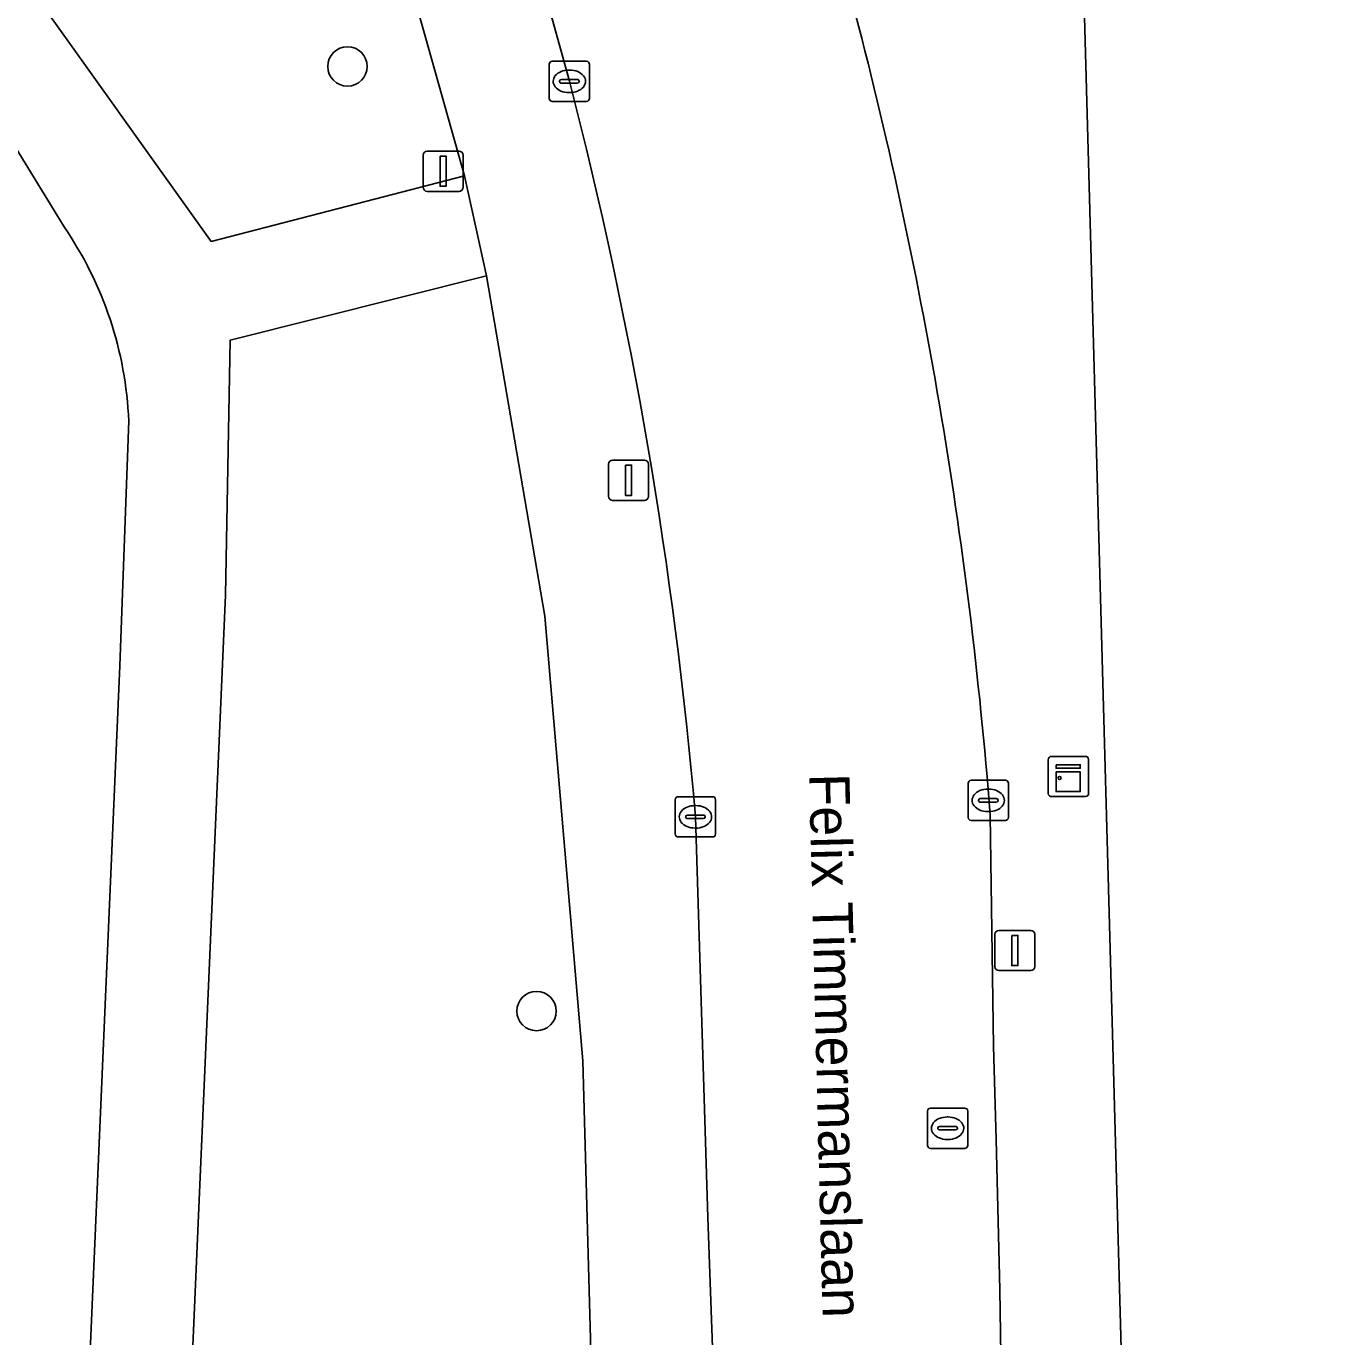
# Model space of a CAD drawing. Extents: x 161258 to 161838, y 380833 to 381727.
# Drawn here: x 161547.08 to 161579.31, y 381304.76 to 381337.3 of the extents above; entities that cross this region are included whole.
import ezdxf

# ---------------------------------------------------------------- set-up
doc = ezdxf.new("R2010")
doc.units = 0
for name, color, linetype in [('IMGEO_Boom', 7, 'Continuous'), ('IMGEO_Erf', 7, 'Continuous'), ('IMGEO_Groenvoorziening', 7, 'Continuous'), ('IMGEO_Kast', 7, 'Continuous'), ('IMGEO_Kolk', 7, 'Continuous'), ('IMGEO_Lichtmast', 7, 'Continuous'), ('IMGEO_Openbare_ruimte_label', 7, 'Continuous'), ('IMGEO_Rijbaan_lokaal_open', 7, 'Continuous'), ('IMGEO_Rioolput', 7, 'Continuous'), ('IMGEO_Verkeersbordpaal', 7, 'Continuous'), ('IMGEO_Voetpad_gesloten', 7, 'Continuous'), ('IMGEO_Voetpad_open', 7, 'Continuous')]:
    doc.layers.add(name, color=color, linetype=linetype)

msp = doc.modelspace()

# ---------------------------------------------------------------- linework, layer by layer
at = {"layer": 'IMGEO_Boom'}
for centre in [(161555.05, 381336.303), (161559.745, 381312.847)]:
    msp.add_circle(centre, 0.489, dxfattribs=at)
at = {"layer": 'IMGEO_Erf'}
msp.add_lwpolyline([(161649.397, 381275.455), (161650.22, 381281.92), (161650.255, 381282.192), (161650.617, 381285.056), (161650.964, 381287.799), (161651.304, 381290.495), (161653.107, 381304.757), (161653.531, 381308.117), (161653.779, 381310.086), (161654.173, 381313.208), (161656.956, 381335.212), (161638.457, 381337.583), (161631.072, 381338.529), (161622.414, 381339.639), (161618.671, 381340.119), (161596.827, 381342.918), (161589.772, 381343.822), (161573.115, 381345.957), (161575.536, 381257.867), (161575.581, 381250), (161575.075, 381232.455), (161573.778, 381197.042)], dxfattribs=at)
at = {"layer": 'IMGEO_Groenvoorziening'}
for points in [[(161548.016, 381332.322), (161543.801, 381339.204), (161540.076, 381345.152), (161529.862, 381362.837), (161527.459, 381367.542), (161522.359, 381377.765), (161521.162, 381381.001), (161516.427, 381396.432), (161510.615, 381415.369), (161509.68, 381415.127)], [(161549.116, 381380.018), (161549.108, 381382.107), (161544.779, 381381.965), (161538.743, 381382.034), (161531.12, 381380.29), (161523.196, 381383.091), (161523.489, 381382.145), (161524.888, 381378.302), (161529.686, 381368.678), (161532.033, 381364.077), (161538.316, 381353.079), (161542.231, 381346.419), (161547.061, 381338.423), (161551.665, 381331.955), (161557.953, 381333.585), (161554.804, 381344.789), (161552.797, 381350.589)], [(161553.579, 381215.917), (161561.286, 381215.348), (161561.314, 381216.115), (161562.157, 381238.191), (161562.402, 381250), (161562.371, 381257.897), (161560.891, 381311.609), (161559.948, 381322.649), (161558.505, 381331.099), (161552.138, 381329.503), (161552.025, 381323.171), (161549.695, 381269.54), (161548.757, 381250), (161548.051, 381233.4)], [(161545.424, 381233.206), (161546.121, 381250), (161547.153, 381269.408), (161549.398, 381321.418), (161549.623, 381327.498)]]:
    msp.add_lwpolyline(points, dxfattribs=at)
msp.add_arc((161540.395, 381327.104), 9.237, 2.4477, 34.4009, dxfattribs=at)
at = {"layer": 'IMGEO_Kast'}
for p, q in [((161572.446, 381318.246), (161572.446, 381319.087)), ((161572.446, 381319.087), (161572.446, 381318.246)), ((161572.521, 381319.171), (161573.362, 381319.171)), ((161573.362, 381319.171), (161572.521, 381319.171)), ((161573.446, 381319.096), (161573.446, 381318.255)), ((161573.446, 381318.255), (161573.446, 381319.096)), ((161573.371, 381318.171), (161572.53, 381318.171)), ((161572.53, 381318.171), (161573.371, 381318.171))]:
    msp.add_line(p, q, dxfattribs=at)
for points in [[(161572.641, 381318.961), (161573.241, 381318.961), (161573.241, 381318.876), (161572.641, 381318.876), (161572.641, 381318.961)], [(161572.641, 381318.786), (161573.241, 381318.786), (161573.241, 381318.297), (161572.641, 381318.297), (161572.641, 381318.786)]]:
    msp.add_lwpolyline(points, dxfattribs=at)
msp.add_circle((161572.725, 381318.635), 0.0377, dxfattribs=at)
for centre, start, end in [((161572.524, 381319.093), 92.4484, 184.2845), ((161572.524, 381319.093), 92.4484, 184.2845), ((161573.368, 381319.093), 2.4484, 94.2845), ((161573.368, 381319.093), 2.4484, 94.2845), ((161572.524, 381318.249), 182.4484, 274.2845), ((161572.524, 381318.249), 182.4484, 274.2845), ((161573.368, 381318.249), 272.4484, 4.2845), ((161573.368, 381318.249), 272.4484, 4.2845)]:
    msp.add_arc(centre, 0.0779, start, end, dxfattribs=at)
at = {"layer": 'IMGEO_Kolk'}
for p, q in [((161560.058, 381335.506), (161560.058, 381336.358)), ((161560.133, 381336.432), (161560.985, 381336.432)), ((161561.059, 381336.358), (161561.059, 381335.506)), ((161560.317, 381335.926), (161560.317, 381335.938)), ((161560.36, 381335.975), (161560.758, 381335.975)), ((161560.546, 381336.212), (161560.571, 381336.212)), ((161560.801, 381335.938), (161560.801, 381335.926)), ((161560.755, 381335.889), (161560.357, 381335.889)), ((161560.569, 381335.652), (161560.544, 381335.652)), ((161560.985, 381335.432), (161560.133, 381335.432)), ((161570.456, 381317.652), (161570.456, 381318.504)), ((161570.531, 381318.578), (161571.383, 381318.578)), ((161570.944, 381318.358), (161570.969, 381318.358)), ((161571.457, 381318.504), (161571.457, 381317.652)), ((161563.187, 381317.243), (161563.187, 381318.095)), ((161563.262, 381318.169), (161564.114, 381318.169)), ((161564.188, 381318.095), (161564.188, 381317.243)), ((161570.715, 381318.072), (161570.715, 381318.084)), ((161571.153, 381318.035), (161570.755, 381318.035)), ((161570.758, 381318.121), (161571.156, 381318.121)), ((161571.199, 381318.084), (161571.199, 381318.072)), ((161563.489, 381317.712), (161563.887, 381317.712)), ((161563.675, 381317.949), (161563.7, 381317.949)), ((161570.967, 381317.798), (161570.942, 381317.798)), ((161563.446, 381317.663), (161563.446, 381317.675)), ((161563.884, 381317.626), (161563.486, 381317.626)), ((161563.698, 381317.389), (161563.673, 381317.389)), ((161563.93, 381317.675), (161563.93, 381317.663)), ((161571.383, 381317.578), (161570.531, 381317.578)), ((161564.114, 381317.169), (161563.262, 381317.169))]:
    msp.add_line(p, q, dxfattribs=at)
for points in [[(161560.058, 381335.506), (161560.058, 381336.358)], [(161560.133, 381336.432), (161560.985, 381336.432)], [(161561.059, 381336.358), (161561.059, 381335.506)], [(161560.985, 381335.432), (161560.133, 381335.432)], [(161570.456, 381317.652), (161570.456, 381318.504)], [(161570.531, 381318.578), (161571.383, 381318.578)], [(161571.457, 381318.504), (161571.457, 381317.652)], [(161563.187, 381317.243), (161563.187, 381318.095)], [(161563.262, 381318.169), (161564.114, 381318.169)], [(161564.188, 381318.095), (161564.188, 381317.243)], [(161571.383, 381317.578), (161570.531, 381317.578)], [(161564.114, 381317.169), (161563.262, 381317.169)]]:
    msp.add_lwpolyline(points, dxfattribs=at)
for centre, radius, start, end in [((161560.135, 381336.356), 0.0765, 91.552, 178.448), ((161560.135, 381336.356), 0.0765, 91.552, 178.448), ((161560.983, 381336.356), 0.0765, 1.552, 88.448), ((161560.983, 381336.356), 0.0765, 1.552, 88.448), ((161560.357, 381335.935), 0.0403, 85.8775, 175.7526), ((161560.354, 381335.925), 0.0366, 178.938, 274.7102), ((161560.758, 381335.932), 0.043, 264.8664, 352.4533), ((161560.762, 381335.937), 0.0386, 1.7309, 96.639), ((161560.135, 381335.508), 0.0765, 181.552, 268.448), ((161560.135, 381335.508), 0.0765, 181.552, 268.448), ((161560.983, 381335.508), 0.0765, 271.552, 358.448), ((161560.983, 381335.508), 0.0765, 271.552, 358.448), ((161570.533, 381318.502), 0.0765, 91.552, 178.448), ((161570.533, 381318.502), 0.0765, 91.552, 178.448), ((161571.381, 381318.502), 0.0765, 1.552, 88.448), ((161571.381, 381318.502), 0.0765, 1.552, 88.448), ((161563.264, 381318.093), 0.0765, 91.552, 178.448), ((161563.264, 381318.093), 0.0765, 91.552, 178.448), ((161564.112, 381318.093), 0.0765, 1.552, 88.448), ((161564.112, 381318.093), 0.0765, 1.552, 88.448), ((161570.755, 381318.081), 0.0403, 85.8775, 175.7526), ((161570.752, 381318.071), 0.0366, 178.938, 274.7102), ((161571.156, 381318.078), 0.043, 264.8664, 352.4533), ((161571.16, 381318.083), 0.0386, 1.7309, 96.639), ((161563.486, 381317.672), 0.0403, 85.8775, 175.7526), ((161563.891, 381317.674), 0.0386, 1.7309, 96.639), ((161563.483, 381317.662), 0.0366, 178.938, 274.7102), ((161563.887, 381317.669), 0.043, 264.8664, 352.4533), ((161570.533, 381317.654), 0.0765, 181.552, 268.448), ((161570.533, 381317.654), 0.0765, 181.552, 268.448), ((161571.381, 381317.654), 0.0765, 271.552, 358.448), ((161571.381, 381317.654), 0.0765, 271.552, 358.448), ((161563.264, 381317.245), 0.0765, 181.552, 268.448), ((161563.264, 381317.245), 0.0765, 181.552, 268.448), ((161564.112, 381317.245), 0.0765, 271.552, 358.448), ((161564.112, 381317.245), 0.0765, 271.552, 358.448)]:
    msp.add_arc(centre, radius, start, end, dxfattribs=at)
for centre, major_axis, ratio, start_param, end_param in [((161560.545, 381335.932), (-0.387, 0.002), 0.722429, 4.712389, 7.853982), ((161560.57, 381335.932), (-0.39, 0.002), 0.717154, 1.570796, 4.712389), ((161570.943, 381318.078), (-0.387, 0.002), 0.722429, 4.712389, 7.853982), ((161570.968, 381318.078), (-0.39, 0.002), 0.717154, 1.570796, 4.712389), ((161563.674, 381317.669), (-0.387, 0.002), 0.722429, 4.712389, 7.853982), ((161563.699, 381317.669), (-0.39, 0.002), 0.717154, 1.570796, 4.712389)]:
    msp.add_ellipse(centre, major_axis=major_axis, ratio=ratio, start_param=start_param, end_param=end_param, dxfattribs=at)
at = {"layer": 'IMGEO_Lichtmast'}
for p, q in [((161561.632, 381326.527), (161562.422, 381326.527)), ((161562.422, 381326.527), (161561.632, 381326.527)), ((161561.532, 381325.627), (161561.532, 381326.427)), ((161561.532, 381326.427), (161561.532, 381325.627)), ((161562.522, 381326.427), (161562.522, 381325.627)), ((161562.522, 381325.627), (161562.522, 381326.427)), ((161562.422, 381325.527), (161561.632, 381325.527)), ((161561.632, 381325.527), (161562.422, 381325.527)), ((161571.221, 381314.85), (161572.011, 381314.85)), ((161572.011, 381314.85), (161571.221, 381314.85)), ((161571.121, 381313.95), (161571.121, 381314.75)), ((161571.121, 381314.75), (161571.121, 381313.95)), ((161572.111, 381314.75), (161572.111, 381313.95)), ((161572.111, 381313.95), (161572.111, 381314.75)), ((161572.011, 381313.85), (161571.221, 381313.85)), ((161571.221, 381313.85), (161572.011, 381313.85))]:
    msp.add_line(p, q, dxfattribs=at)
for points in [[(161561.952, 381326.402), (161562.102, 381326.402), (161562.102, 381325.652), (161561.952, 381325.652), (161561.952, 381326.402)], [(161571.541, 381314.725), (161571.691, 381314.725), (161571.691, 381313.975), (161571.541, 381313.975), (161571.541, 381314.725)]]:
    msp.add_lwpolyline(points, dxfattribs=at)
for centre, start, end in [((161561.632, 381326.427), 90, 180), ((161561.632, 381326.427), 90, 180), ((161562.422, 381326.427), 0, 90), ((161562.422, 381326.427), 360, 90), ((161561.632, 381325.627), 180, 270), ((161561.632, 381325.627), 180, 270), ((161562.422, 381325.627), 270, 0), ((161562.422, 381325.627), 270, 0), ((161571.221, 381314.75), 90, 180), ((161571.221, 381314.75), 90, 180), ((161572.011, 381314.75), 0, 90), ((161572.011, 381314.75), 360, 90), ((161571.221, 381313.95), 180, 270), ((161571.221, 381313.95), 180, 270), ((161572.011, 381313.95), 270, 0), ((161572.011, 381313.95), 270, 0)]:
    msp.add_arc(centre, 0.1, start, end, dxfattribs=at)
at = {"layer": 'IMGEO_Rijbaan_lokaal_open'}
for points in [[(161567.573, 381337.935), (161566.996, 381340.113), (161559.926, 381338.237), (161560.56, 381335.932)], [(161572.007, 381272.353), (161571.937, 381276.234), (161571.841, 381280.385), (161571.71, 381285.385), (161571.552, 381289.803), (161571.367, 381297.22), (161571.333, 381300.008), (161571.247, 381305.925), (161571.149, 381309.659), (161571.088, 381311.972), (161571.005, 381317.713)], [(161563.689, 381317.669), (161563.992, 381307.722), (161564.285, 381299.662), (161564.523, 381289.706), (161564.858, 381278.272), (161564.966, 381273.754), (161565.177, 381265.56), (161565.325, 381258.823), (161565.412, 381254.146), (161565.337, 381250), (161565.241, 381243.283), (161564.974, 381233.421), (161564.784, 381227.236), (161564.503, 381220.58)]]:
    msp.add_lwpolyline(points, dxfattribs=at)
for centre, radius, start, end in [((161457.404, 381308.835), 113.947, 4.46846, 14.79602), ((161452.758, 381308.063), 111.347, 4.9493, 14.49489)]:
    msp.add_arc(centre, radius, start, end, dxfattribs=at)
at = {"layer": 'IMGEO_Rioolput'}
for p, q in [((161569.447, 381309.511), (161569.447, 381310.363)), ((161569.522, 381310.437), (161570.374, 381310.437)), ((161569.935, 381310.217), (161569.96, 381310.217)), ((161570.448, 381310.363), (161570.448, 381309.511)), ((161569.706, 381309.931), (161569.706, 381309.943)), ((161570.144, 381309.894), (161569.746, 381309.894)), ((161569.749, 381309.98), (161570.147, 381309.98)), ((161570.19, 381309.943), (161570.19, 381309.931)), ((161569.958, 381309.657), (161569.933, 381309.657)), ((161570.374, 381309.437), (161569.522, 381309.437))]:
    msp.add_line(p, q, dxfattribs=at)
for points in [[(161569.447, 381309.511), (161569.447, 381310.363)], [(161569.522, 381310.437), (161570.374, 381310.437)], [(161570.448, 381310.363), (161570.448, 381309.511)], [(161570.374, 381309.437), (161569.522, 381309.437)]]:
    msp.add_lwpolyline(points, dxfattribs=at)
for centre, radius, start, end in [((161569.524, 381310.361), 0.0765, 91.552, 178.448), ((161569.524, 381310.361), 0.0765, 91.552, 178.448), ((161570.372, 381310.361), 0.0765, 1.552, 88.448), ((161570.372, 381310.361), 0.0765, 1.552, 88.448), ((161569.746, 381309.94), 0.0403, 85.8775, 175.7526), ((161569.743, 381309.93), 0.0366, 178.938, 274.7102), ((161570.147, 381309.937), 0.043, 264.8664, 352.4533), ((161570.151, 381309.942), 0.0386, 1.7309, 96.639), ((161569.524, 381309.513), 0.0765, 181.552, 268.448), ((161569.524, 381309.513), 0.0765, 181.552, 268.448), ((161570.372, 381309.513), 0.0765, 271.552, 358.448), ((161570.372, 381309.513), 0.0765, 271.552, 358.448)]:
    msp.add_arc(centre, radius, start, end, dxfattribs=at)
for centre, major_axis, ratio, start_param, end_param in [((161569.934, 381309.937), (-0.387, 0.002), 0.722429, 4.712389, 7.853982), ((161569.959, 381309.937), (-0.39, 0.002), 0.717154, 1.570796, 4.712389)]:
    msp.add_ellipse(centre, major_axis=major_axis, ratio=ratio, start_param=start_param, end_param=end_param, dxfattribs=at)
at = {"layer": 'IMGEO_Verkeersbordpaal'}
for p, q in [((161556.931, 381333.3), (161556.931, 381334.1)), ((161556.931, 381334.1), (161556.931, 381333.3)), ((161557.031, 381334.2), (161557.821, 381334.2)), ((161557.821, 381334.2), (161557.031, 381334.2)), ((161557.921, 381334.1), (161557.921, 381333.3)), ((161557.921, 381333.3), (161557.921, 381334.1)), ((161557.821, 381333.2), (161557.031, 381333.2)), ((161557.031, 381333.2), (161557.821, 381333.2))]:
    msp.add_line(p, q, dxfattribs=at)
msp.add_lwpolyline([(161557.351, 381334.075), (161557.501, 381334.075), (161557.501, 381333.325), (161557.351, 381333.325), (161557.351, 381334.075)], dxfattribs=at)
for centre, start, end in [((161557.031, 381334.1), 90, 180), ((161557.031, 381334.1), 90, 180), ((161557.821, 381334.1), 0, 90), ((161557.821, 381334.1), 360, 90), ((161557.031, 381333.3), 180, 270), ((161557.031, 381333.3), 180, 270), ((161557.821, 381333.3), 270, 0), ((161557.821, 381333.3), 270, 0)]:
    msp.add_arc(centre, 0.1, start, end, dxfattribs=at)
at = {"layer": 'IMGEO_Voetpad_gesloten'}
for points in [[(161543.801, 381339.204), (161548.016, 381332.322)], [(161549.695, 381269.54), (161552.025, 381323.171), (161552.138, 381329.503), (161558.505, 381331.099), (161557.953, 381333.585), (161551.665, 381331.955), (161547.061, 381338.423)], [(161549.623, 381327.498), (161549.398, 381321.418), (161547.153, 381269.408), (161546.121, 381250), (161545.424, 381233.206)]]:
    msp.add_lwpolyline(points, dxfattribs=at)
msp.add_arc((161540.395, 381327.104), 9.237, 2.4477, 34.4009, dxfattribs=at)
at = {"layer": 'IMGEO_Voetpad_open'}
for points in [[(161552.797, 381350.589), (161554.804, 381344.789), (161557.953, 381333.585), (161558.505, 381331.099), (161559.948, 381322.649), (161560.891, 381311.609), (161562.371, 381257.897), (161562.402, 381250), (161562.157, 381238.191), (161561.314, 381216.115), (161561.286, 381215.348), (161561.199, 381212.989), (161561.183, 381212.553), (161560.87, 381203.99), (161560.54, 381195.569), (161560.289, 381187.309), (161560.131, 381179.362), (161560.133, 381176.238), (161563.163, 381176.176), (161563.158, 381177.603)], [(161573.778, 381197.042), (161575.075, 381232.455), (161575.581, 381250), (161575.536, 381257.867), (161573.115, 381345.957)], [(161560.56, 381335.932), (161559.926, 381338.237)], [(161571.005, 381317.713), (161571.088, 381311.972), (161571.149, 381309.659), (161571.247, 381305.925), (161571.333, 381300.008), (161571.367, 381297.22), (161571.552, 381289.803), (161571.71, 381285.385), (161571.841, 381280.385), (161571.937, 381276.234), (161572.007, 381272.353), (161572.171, 381266.916), (161572.516, 381257.53), (161572.49, 381252.317), (161572.562, 381247.819), (161571.478, 381215.409), (161571.305, 381211.541), (161570.775, 381198.479), (161570.721, 381195.892)], [(161565.241, 381243.283), (161565.337, 381250), (161565.412, 381254.146), (161565.325, 381258.823), (161565.177, 381265.56), (161564.966, 381273.754), (161564.858, 381278.272), (161564.523, 381289.706), (161564.285, 381299.662), (161563.992, 381307.722), (161563.689, 381317.669)]]:
    msp.add_lwpolyline(points, dxfattribs=at)
for centre, radius, start, end in [((161457.404, 381308.835), 113.947, 4.46846, 14.79602), ((161452.758, 381308.063), 111.347, 4.9493, 14.49489)]:
    msp.add_arc(centre, radius, start, end, dxfattribs=at)

# ---------------------------------------------------------------- texts
at = {"layer": 'IMGEO_Openbare_ruimte_label'}
msp.add_text('Felix Timmermanslaan', height=1, rotation=271.4321, dxfattribs=at).set_placement((161566.509, 381318.738))

doc.saveas('drawing.dxf')
